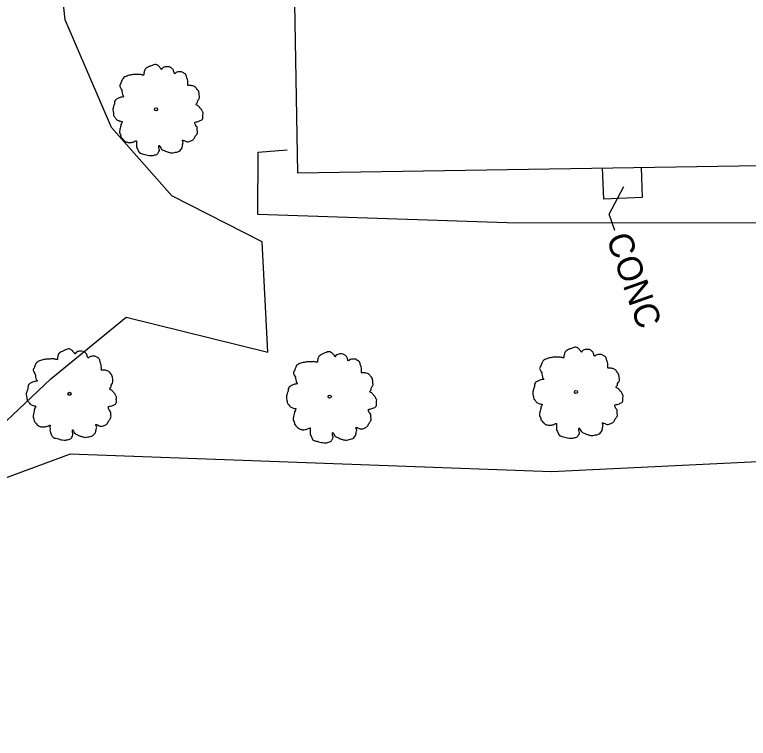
# Model space of a CAD drawing. Extents: x 2004847 to 2009016, y 1134161 to 1140101.
# Drawn here: x 2006332 to 2006449.6, y 1137314.8 to 1137430.7 of the extents above; entities that cross this region are included whole.
import ezdxf

# ---------------------------------------------------------------- set-up
doc = ezdxf.new("R2010")
doc.units = 0
for name, color, linetype in [('RD_EX_Bldg', 7, 'Continuous'), ('RD_EX_Conc', 7, 'Continuous'), ('RD_EX_Driveway', 7, 'Continuous'), ('RD_EX_VEG', 7, 'Continuous'), ('RD_Sketch3', 7, 'Continuous')]:
    doc.layers.add(name, color=color, linetype=linetype)

msp = doc.modelspace()

# ---------------------------------------------------------------- linework, layer by layer
at = {"layer": 'RD_EX_Bldg'}
msp.add_lwpolyline([(2006371.89, 1137715.52), (2006377.36, 1137405.37), (2007270.04, 1137419.53), (2007268.52, 1137729.51), (2007210.95, 1137728.61)], dxfattribs=at)
at = {"layer": 'RD_EX_Conc'}
for p, q in [((2006426.24, 1137406.15), (2006426.45, 1137401.15)), ((2006432.45, 1137406.25), (2006432.65, 1137401.41)), ((2006432.65, 1137401.41), (2006426.45, 1137401.15))]:
    msp.add_line(p, q, dxfattribs=at)
at = {"layer": 'RD_EX_Driveway'}
msp.add_lwpolyline([(2006320, 1137461.45), (2006324.08, 1137411.61), (2006324.34, 1137386.71), (2006308.63, 1137371.07), (2006287.09, 1137362.98), (2006291.81, 1137347.5), (2006305.24, 1137351.22), (2006324.46, 1137359.78), (2006337.82, 1137372.35), (2006349.89, 1137382.22), (2006372.62, 1137376.62), (2006371.69, 1137394.32), (2006357.21, 1137401.66), (2006347.58, 1137412.64), (2006340.11, 1137429.9), (2006337.43, 1137455.2)], dxfattribs=at)
at = {"layer": 'RD_EX_VEG'}
for points in [[(2007282.5, 1137416.98), (2007281.09, 1137410.1), (2007242.65, 1137408.85), (2007161.61, 1137408.11), (2007074.33, 1137407.29), (2006993.94, 1137406.09), (2006904.98, 1137405.1), (2006825.9, 1137403.95), (2006734.64, 1137402.12), (2006651.81, 1137401.28), (2006571.17, 1137400.1), (2006488.04, 1137397.36), (2006412.6, 1137397.32), (2006371.03, 1137398.69)], [(2006371.03, 1137398.69), (2006371.08, 1137408.7), (2006375.7, 1137409.05)], [(2006737.12, 1137362.87), (2006655.14, 1137367.42), (2006573.07, 1137360.44), (2006492.05, 1137361.03), (2006418.07, 1137357.44), (2006340.96, 1137360.31)], [(2006340.96, 1137360.31), (2006313.74, 1137350.25), (2006288.58, 1137344.89), (2006287.9, 1137319.66), (2006304.95, 1137291.42), (2006332.05, 1137276.17)]]:
    msp.add_lwpolyline(points, dxfattribs=at)
for centre, radius in [((2006354.7, 1137415.53), 0.25), ((2006354.68, 1137415.51), 0.0001), ((2006340.83, 1137369.96), 0.25), ((2006422.02, 1137370.24), 0.25), ((2006422.01, 1137370.22), 0.0001), ((2006340.82, 1137369.94), 0.0001), ((2006382.53, 1137369.52), 0.25), ((2006382.52, 1137369.5), 0.0001)]:
    msp.add_circle(centre, radius, dxfattribs=at)
for points in [[(2006354.83, 1137422.7), (2006354.53, 1137422.72), (2006354.2, 1137422.62), (2006353.95, 1137422.52), (2006353.73, 1137422.45), (2006353.5, 1137422.35), (2006353.2, 1137422.17), (2006352.98, 1137421.97), (2006352.85, 1137421.72), (2006352.8, 1137421.5), (2006352.75, 1137421.22), (2006352.75, 1137421.05), (2006352.63, 1137421.02), (2006352.48, 1137421.05), (2006352.23, 1137421.12), (2006351.98, 1137421.12), (2006351.73, 1137421.12), (2006351.38, 1137421.1), (2006351.03, 1137421.1), (2006350.76, 1137421.05), (2006350.43, 1137421), (2006350.06, 1137420.87), (2006349.71, 1137420.75), (2006349.41, 1137420.5), (2006349.16, 1137420.02), (2006349.03, 1137419.67), (2006348.88, 1137419.42), (2006349.03, 1137418.97), (2006349.21, 1137418.63), (2006349.23, 1137418.43), (2006349.31, 1137418), (2006349.41, 1137417.78), (2006349.53, 1137417.58), (2006349.46, 1137417.55), (2006349.08, 1137417.5), (2006348.78, 1137417.4), (2006348.36, 1137417.18), (2006348.13, 1137416.95), (2006348.03, 1137416.63), (2006348.01, 1137416.28), (2006347.91, 1137416.08), (2006347.83, 1137415.8), (2006347.81, 1137415.73), (2006347.76, 1137415.4), (2006347.86, 1137414.95), (2006347.88, 1137414.6), (2006348.01, 1137414.38), (2006348.16, 1137414.2), (2006348.33, 1137413.95), (2006348.73, 1137413.73), (2006349.06, 1137413.63), (2006349.26, 1137413.6), (2006349.08, 1137413.1), (2006349.03, 1137412.75), (2006348.91, 1137412.35), (2006348.91, 1137412.28), (2006348.86, 1137411.8), (2006349.01, 1137411.48), (2006349.08, 1137411.1), (2006349.26, 1137410.88), (2006349.53, 1137410.58), (2006349.86, 1137410.35), (2006350.36, 1137410.23), (2006350.76, 1137410.25), (2006351.33, 1137410.43), (2006351.58, 1137410.5), (2006351.56, 1137410.33), (2006351.58, 1137409.95), (2006351.58, 1137409.53), (2006351.73, 1137409.2), (2006351.83, 1137408.93), (2006351.98, 1137408.68), (2006352.31, 1137408.45), (2006352.7, 1137408.38), (2006353.13, 1137408.23), (2006353.58, 1137408.15), (2006354.08, 1137408.13), (2006354.68, 1137408.28), (2006354.95, 1137408.4), (2006355.05, 1137408.58), (2006355.25, 1137408.95), (2006355.2, 1137409.18), (2006355.23, 1137409.78), (2006355.33, 1137409.6), (2006355.5, 1137409.25), (2006356, 1137408.95), (2006356.4, 1137408.78), (2006356.88, 1137408.63), (2006357.18, 1137408.55), (2006357.65, 1137408.63), (2006358.03, 1137408.7), (2006358.4, 1137408.83), (2006358.7, 1137409.1), (2006358.88, 1137409.38), (2006358.93, 1137409.65), (2006359, 1137410.03), (2006359.05, 1137410.2)], [(2006359.05, 1137410.2), (2006358.98, 1137410.38), (2006358.93, 1137410.63), (2006359, 1137410.6), (2006359.18, 1137410.55), (2006359.45, 1137410.43), (2006359.68, 1137410.35), (2006360, 1137410.38), (2006360.28, 1137410.48), (2006360.73, 1137410.75), (2006361, 1137411.23), (2006361.28, 1137411.63), (2006361.35, 1137411.95), (2006361.3, 1137412.18), (2006361.28, 1137412.68), (2006361.08, 1137412.93), (2006361.03, 1137413.05), (2006360.93, 1137413.45), (2006361, 1137413.5), (2006361.28, 1137413.55), (2006361.65, 1137413.68), (2006361.93, 1137413.8), (2006362.15, 1137413.98), (2006362.23, 1137414.2), (2006362.2, 1137414.6), (2006362.25, 1137415), (2006362.18, 1137415.15), (2006362.08, 1137415.3), (2006362, 1137415.5), (2006361.85, 1137415.65), (2006361.75, 1137415.8), (2006361.65, 1137415.9), (2006361.53, 1137416.05), (2006361.35, 1137416.18), (2006361.2, 1137416.23), (2006361.15, 1137416.38), (2006361.3, 1137416.58), (2006361.35, 1137416.68), (2006361.38, 1137416.9), (2006361.6, 1137417.25), (2006361.65, 1137417.65), (2006361.6, 1137418.08), (2006361.55, 1137418.35), (2006361.4, 1137418.63), (2006361.2, 1137418.87), (2006361.08, 1137419.05), (2006360.9, 1137419.17), (2006360.58, 1137419.3), (2006360.33, 1137419.35), (2006359.98, 1137419.35), (2006359.78, 1137419.4), (2006359.8, 1137419.45), (2006359.8, 1137419.6), (2006359.8, 1137419.87), (2006359.73, 1137420.32), (2006359.58, 1137420.82), (2006359.58, 1137420.85), (2006359.48, 1137421.1), (2006359.25, 1137421.3), (2006359.08, 1137421.4), (2006358.88, 1137421.52), (2006358.63, 1137421.55), (2006358.33, 1137421.55), (2006358.05, 1137421.5), (2006357.85, 1137421.4), (2006357.68, 1137421.27), (2006357.6, 1137421.42), (2006357.5, 1137421.72), (2006357.45, 1137421.87), (2006357.3, 1137422.05), (2006357.08, 1137422.25), (2006356.63, 1137422.37), (2006356, 1137422.3), (2006355.7, 1137422.1), (2006355.55, 1137421.92), (2006355.5, 1137422.05), (2006355.3, 1137422.25), (2006355.2, 1137422.42), (2006355.03, 1137422.55), (2006354.88, 1137422.65), (2006354.78, 1137422.7)], [(2006340.96, 1137377.12), (2006340.66, 1137377.15), (2006340.34, 1137377.05), (2006340.09, 1137376.95), (2006339.86, 1137376.87), (2006339.64, 1137376.77), (2006339.34, 1137376.6), (2006339.11, 1137376.4), (2006338.99, 1137376.15), (2006338.94, 1137375.92), (2006338.89, 1137375.65), (2006338.89, 1137375.47), (2006338.76, 1137375.45), (2006338.61, 1137375.47), (2006338.36, 1137375.55), (2006338.11, 1137375.55), (2006337.86, 1137375.55), (2006337.51, 1137375.52), (2006337.16, 1137375.52), (2006336.89, 1137375.47), (2006336.56, 1137375.42), (2006336.19, 1137375.3), (2006335.84, 1137375.17), (2006335.54, 1137374.92), (2006335.29, 1137374.45), (2006335.17, 1137374.1), (2006335.02, 1137373.85), (2006335.17, 1137373.4), (2006335.34, 1137373.05), (2006335.37, 1137372.85), (2006335.44, 1137372.43), (2006335.54, 1137372.2), (2006335.67, 1137372), (2006335.59, 1137371.98), (2006335.22, 1137371.93), (2006334.92, 1137371.83), (2006334.49, 1137371.6), (2006334.27, 1137371.38), (2006334.17, 1137371.05), (2006334.14, 1137370.7), (2006334.04, 1137370.5), (2006333.97, 1137370.23), (2006333.94, 1137370.15), (2006333.89, 1137369.83), (2006333.99, 1137369.38), (2006334.02, 1137369.03), (2006334.14, 1137368.8), (2006334.29, 1137368.63), (2006334.47, 1137368.38), (2006334.87, 1137368.15), (2006335.19, 1137368.05), (2006335.39, 1137368.03), (2006335.22, 1137367.53), (2006335.17, 1137367.18), (2006335.04, 1137366.78), (2006335.04, 1137366.7), (2006334.99, 1137366.23), (2006335.14, 1137365.9), (2006335.22, 1137365.53), (2006335.39, 1137365.3), (2006335.67, 1137365), (2006335.99, 1137364.78), (2006336.49, 1137364.65), (2006336.89, 1137364.68), (2006337.46, 1137364.85), (2006337.71, 1137364.93), (2006337.69, 1137364.75), (2006337.71, 1137364.38), (2006337.71, 1137363.95), (2006337.86, 1137363.63), (2006337.96, 1137363.35), (2006338.11, 1137363.1), (2006338.44, 1137362.88), (2006338.84, 1137362.8), (2006339.26, 1137362.65), (2006339.71, 1137362.58), (2006340.21, 1137362.55), (2006340.81, 1137362.7), (2006341.09, 1137362.83), (2006341.19, 1137363), (2006341.39, 1137363.38), (2006341.34, 1137363.6), (2006341.36, 1137364.2), (2006341.46, 1137364.03), (2006341.64, 1137363.68), (2006342.14, 1137363.38), (2006342.54, 1137363.2), (2006343.01, 1137363.05), (2006343.31, 1137362.98), (2006343.79, 1137363.05), (2006344.16, 1137363.13), (2006344.54, 1137363.25), (2006344.84, 1137363.53), (2006345.01, 1137363.8), (2006345.06, 1137364.08), (2006345.14, 1137364.45), (2006345.19, 1137364.63)], [(2006345.19, 1137364.63), (2006345.11, 1137364.8), (2006345.06, 1137365.05), (2006345.14, 1137365.03), (2006345.31, 1137364.98), (2006345.59, 1137364.85), (2006345.81, 1137364.78), (2006346.14, 1137364.8), (2006346.41, 1137364.9), (2006346.86, 1137365.18), (2006347.14, 1137365.65), (2006347.41, 1137366.05), (2006347.49, 1137366.38), (2006347.44, 1137366.6), (2006347.41, 1137367.1), (2006347.21, 1137367.35), (2006347.16, 1137367.48), (2006347.06, 1137367.88), (2006347.14, 1137367.93), (2006347.41, 1137367.98), (2006347.78, 1137368.1), (2006348.06, 1137368.23), (2006348.28, 1137368.4), (2006348.36, 1137368.63), (2006348.33, 1137369.03), (2006348.38, 1137369.43), (2006348.31, 1137369.58), (2006348.21, 1137369.73), (2006348.13, 1137369.93), (2006347.98, 1137370.08), (2006347.88, 1137370.23), (2006347.78, 1137370.33), (2006347.66, 1137370.48), (2006347.49, 1137370.6), (2006347.34, 1137370.65), (2006347.29, 1137370.8), (2006347.44, 1137371), (2006347.49, 1137371.1), (2006347.51, 1137371.33), (2006347.74, 1137371.68), (2006347.78, 1137372.08), (2006347.74, 1137372.5), (2006347.69, 1137372.78), (2006347.54, 1137373.05), (2006347.34, 1137373.3), (2006347.21, 1137373.47), (2006347.04, 1137373.6), (2006346.71, 1137373.72), (2006346.46, 1137373.77), (2006346.11, 1137373.77), (2006345.91, 1137373.82), (2006345.94, 1137373.87), (2006345.94, 1137374.02), (2006345.94, 1137374.3), (2006345.86, 1137374.75), (2006345.71, 1137375.25), (2006345.71, 1137375.27), (2006345.61, 1137375.52), (2006345.39, 1137375.72), (2006345.21, 1137375.82), (2006345.01, 1137375.95), (2006344.76, 1137375.97), (2006344.46, 1137375.97), (2006344.19, 1137375.92), (2006343.99, 1137375.82), (2006343.81, 1137375.7), (2006343.74, 1137375.85), (2006343.64, 1137376.15), (2006343.59, 1137376.3), (2006343.44, 1137376.47), (2006343.21, 1137376.67), (2006342.76, 1137376.8), (2006342.14, 1137376.72), (2006341.84, 1137376.52), (2006341.69, 1137376.35), (2006341.64, 1137376.47), (2006341.44, 1137376.67), (2006341.34, 1137376.85), (2006341.16, 1137376.97), (2006341.01, 1137377.07), (2006340.91, 1137377.12)], [(2006422.15, 1137377.41), (2006421.85, 1137377.43), (2006421.53, 1137377.33), (2006421.28, 1137377.23), (2006421.05, 1137377.16), (2006420.83, 1137377.06), (2006420.53, 1137376.88), (2006420.3, 1137376.68), (2006420.18, 1137376.43), (2006420.13, 1137376.21), (2006420.08, 1137375.93), (2006420.08, 1137375.76), (2006419.95, 1137375.73), (2006419.8, 1137375.76), (2006419.55, 1137375.83), (2006419.3, 1137375.83), (2006419.05, 1137375.83), (2006418.7, 1137375.81), (2006418.35, 1137375.81), (2006418.08, 1137375.76), (2006417.75, 1137375.71), (2006417.38, 1137375.58), (2006417.03, 1137375.46), (2006416.73, 1137375.21), (2006416.48, 1137374.73), (2006416.35, 1137374.38), (2006416.2, 1137374.13), (2006416.35, 1137373.68), (2006416.53, 1137373.33), (2006416.55, 1137373.13), (2006416.63, 1137372.71), (2006416.73, 1137372.48), (2006416.85, 1137372.28), (2006416.78, 1137372.26), (2006416.4, 1137372.21), (2006416.1, 1137372.11), (2006415.68, 1137371.88), (2006415.45, 1137371.66), (2006415.35, 1137371.33), (2006415.33, 1137370.98), (2006415.23, 1137370.78), (2006415.15, 1137370.51), (2006415.13, 1137370.43), (2006415.08, 1137370.11), (2006415.18, 1137369.66), (2006415.2, 1137369.31), (2006415.33, 1137369.08), (2006415.48, 1137368.91), (2006415.65, 1137368.66), (2006416.05, 1137368.43), (2006416.38, 1137368.33), (2006416.58, 1137368.31), (2006416.4, 1137367.81), (2006416.35, 1137367.46), (2006416.23, 1137367.06), (2006416.23, 1137366.98), (2006416.18, 1137366.51), (2006416.33, 1137366.19), (2006416.4, 1137365.81), (2006416.58, 1137365.59), (2006416.85, 1137365.29), (2006417.18, 1137365.06), (2006417.68, 1137364.94), (2006418.08, 1137364.96), (2006418.65, 1137365.14), (2006418.9, 1137365.21), (2006418.88, 1137365.04), (2006418.9, 1137364.66), (2006418.9, 1137364.24), (2006419.05, 1137363.91), (2006419.15, 1137363.64), (2006419.3, 1137363.39), (2006419.63, 1137363.16), (2006420.03, 1137363.09), (2006420.45, 1137362.94), (2006420.9, 1137362.86), (2006421.4, 1137362.84), (2006422, 1137362.99), (2006422.28, 1137363.11), (2006422.38, 1137363.29), (2006422.58, 1137363.66), (2006422.53, 1137363.89), (2006422.55, 1137364.49), (2006422.65, 1137364.31), (2006422.83, 1137363.96), (2006423.33, 1137363.66), (2006423.73, 1137363.49), (2006424.2, 1137363.34), (2006424.5, 1137363.26), (2006424.97, 1137363.34), (2006425.35, 1137363.41), (2006425.72, 1137363.54), (2006426.02, 1137363.81), (2006426.2, 1137364.09), (2006426.25, 1137364.36), (2006426.32, 1137364.74), (2006426.37, 1137364.91)], [(2006426.37, 1137364.91), (2006426.3, 1137365.09), (2006426.25, 1137365.34), (2006426.32, 1137365.31), (2006426.5, 1137365.26), (2006426.77, 1137365.14), (2006427, 1137365.06), (2006427.32, 1137365.09), (2006427.6, 1137365.19), (2006428.05, 1137365.46), (2006428.32, 1137365.94), (2006428.6, 1137366.34), (2006428.67, 1137366.66), (2006428.62, 1137366.88), (2006428.6, 1137367.38), (2006428.4, 1137367.63), (2006428.35, 1137367.76), (2006428.25, 1137368.16), (2006428.32, 1137368.21), (2006428.6, 1137368.26), (2006428.97, 1137368.38), (2006429.25, 1137368.51), (2006429.47, 1137368.68), (2006429.55, 1137368.91), (2006429.52, 1137369.31), (2006429.57, 1137369.71), (2006429.5, 1137369.86), (2006429.4, 1137370.01), (2006429.32, 1137370.21), (2006429.17, 1137370.36), (2006429.07, 1137370.51), (2006428.97, 1137370.61), (2006428.85, 1137370.76), (2006428.67, 1137370.88), (2006428.52, 1137370.93), (2006428.47, 1137371.08), (2006428.62, 1137371.28), (2006428.67, 1137371.38), (2006428.7, 1137371.61), (2006428.92, 1137371.96), (2006428.97, 1137372.36), (2006428.92, 1137372.78), (2006428.87, 1137373.06), (2006428.72, 1137373.33), (2006428.52, 1137373.58), (2006428.4, 1137373.76), (2006428.22, 1137373.88), (2006427.9, 1137374.01), (2006427.65, 1137374.06), (2006427.3, 1137374.06), (2006427.1, 1137374.11), (2006427.12, 1137374.16), (2006427.12, 1137374.31), (2006427.12, 1137374.58), (2006427.05, 1137375.03), (2006426.9, 1137375.53), (2006426.9, 1137375.56), (2006426.8, 1137375.81), (2006426.57, 1137376.01), (2006426.4, 1137376.11), (2006426.2, 1137376.23), (2006425.95, 1137376.26), (2006425.65, 1137376.26), (2006425.37, 1137376.21), (2006425.17, 1137376.11), (2006425, 1137375.98), (2006424.92, 1137376.13), (2006424.82, 1137376.43), (2006424.77, 1137376.58), (2006424.62, 1137376.76), (2006424.4, 1137376.96), (2006423.95, 1137377.08), (2006423.33, 1137377.01), (2006423.03, 1137376.81), (2006422.88, 1137376.63), (2006422.83, 1137376.76), (2006422.63, 1137376.96), (2006422.53, 1137377.13), (2006422.35, 1137377.26), (2006422.2, 1137377.36), (2006422.1, 1137377.41)], [(2006382.66, 1137376.68), (2006382.36, 1137376.71), (2006382.04, 1137376.61), (2006381.79, 1137376.51), (2006381.56, 1137376.43), (2006381.34, 1137376.33), (2006381.04, 1137376.16), (2006380.81, 1137375.96), (2006380.69, 1137375.71), (2006380.64, 1137375.48), (2006380.59, 1137375.21), (2006380.59, 1137375.03), (2006380.46, 1137375.01), (2006380.31, 1137375.03), (2006380.06, 1137375.11), (2006379.81, 1137375.11), (2006379.56, 1137375.11), (2006379.21, 1137375.08), (2006378.86, 1137375.08), (2006378.59, 1137375.03), (2006378.26, 1137374.98), (2006377.89, 1137374.86), (2006377.54, 1137374.73), (2006377.24, 1137374.48), (2006376.99, 1137374.01), (2006376.87, 1137373.66), (2006376.72, 1137373.41), (2006376.87, 1137372.96), (2006377.04, 1137372.61), (2006377.07, 1137372.41), (2006377.14, 1137371.99), (2006377.24, 1137371.76), (2006377.37, 1137371.56), (2006377.29, 1137371.54), (2006376.92, 1137371.49), (2006376.62, 1137371.39), (2006376.19, 1137371.16), (2006375.97, 1137370.94), (2006375.87, 1137370.61), (2006375.84, 1137370.26), (2006375.74, 1137370.06), (2006375.67, 1137369.79), (2006375.64, 1137369.71), (2006375.59, 1137369.39), (2006375.69, 1137368.94), (2006375.72, 1137368.59), (2006375.84, 1137368.36), (2006375.99, 1137368.19), (2006376.17, 1137367.94), (2006376.57, 1137367.71), (2006376.89, 1137367.61), (2006377.09, 1137367.59), (2006376.92, 1137367.09), (2006376.87, 1137366.74), (2006376.74, 1137366.34), (2006376.74, 1137366.26), (2006376.69, 1137365.79), (2006376.84, 1137365.46), (2006376.92, 1137365.09), (2006377.09, 1137364.86), (2006377.37, 1137364.56), (2006377.69, 1137364.34), (2006378.19, 1137364.21), (2006378.59, 1137364.24), (2006379.16, 1137364.41), (2006379.41, 1137364.49), (2006379.39, 1137364.31), (2006379.41, 1137363.94), (2006379.41, 1137363.51), (2006379.56, 1137363.19), (2006379.66, 1137362.91), (2006379.81, 1137362.66), (2006380.14, 1137362.44), (2006380.54, 1137362.36), (2006380.96, 1137362.21), (2006381.41, 1137362.14), (2006381.91, 1137362.11), (2006382.51, 1137362.26), (2006382.79, 1137362.39), (2006382.89, 1137362.56), (2006383.09, 1137362.94), (2006383.04, 1137363.16), (2006383.06, 1137363.76), (2006383.16, 1137363.59), (2006383.34, 1137363.24), (2006383.84, 1137362.94), (2006384.24, 1137362.76), (2006384.71, 1137362.61), (2006385.01, 1137362.54), (2006385.49, 1137362.61), (2006385.86, 1137362.69), (2006386.24, 1137362.81), (2006386.54, 1137363.09), (2006386.71, 1137363.36), (2006386.76, 1137363.64), (2006386.84, 1137364.01), (2006386.89, 1137364.19)], [(2006386.89, 1137364.19), (2006386.81, 1137364.36), (2006386.76, 1137364.61), (2006386.84, 1137364.59), (2006387.01, 1137364.54), (2006387.29, 1137364.41), (2006387.51, 1137364.34), (2006387.84, 1137364.36), (2006388.11, 1137364.46), (2006388.56, 1137364.74), (2006388.84, 1137365.21), (2006389.11, 1137365.61), (2006389.19, 1137365.94), (2006389.14, 1137366.16), (2006389.11, 1137366.66), (2006388.91, 1137366.91), (2006388.86, 1137367.04), (2006388.76, 1137367.44), (2006388.84, 1137367.49), (2006389.11, 1137367.54), (2006389.48, 1137367.66), (2006389.76, 1137367.79), (2006389.98, 1137367.96), (2006390.06, 1137368.19), (2006390.03, 1137368.59), (2006390.08, 1137368.99), (2006390.01, 1137369.14), (2006389.91, 1137369.29), (2006389.83, 1137369.49), (2006389.68, 1137369.64), (2006389.58, 1137369.79), (2006389.48, 1137369.89), (2006389.36, 1137370.04), (2006389.19, 1137370.16), (2006389.04, 1137370.21), (2006388.99, 1137370.36), (2006389.14, 1137370.56), (2006389.19, 1137370.66), (2006389.21, 1137370.89), (2006389.44, 1137371.24), (2006389.48, 1137371.64), (2006389.44, 1137372.06), (2006389.39, 1137372.34), (2006389.24, 1137372.61), (2006389.04, 1137372.86), (2006388.91, 1137373.03), (2006388.74, 1137373.16), (2006388.41, 1137373.28), (2006388.16, 1137373.33), (2006387.81, 1137373.33), (2006387.61, 1137373.38), (2006387.64, 1137373.43), (2006387.64, 1137373.58), (2006387.64, 1137373.86), (2006387.56, 1137374.31), (2006387.41, 1137374.81), (2006387.41, 1137374.83), (2006387.31, 1137375.08), (2006387.09, 1137375.28), (2006386.91, 1137375.38), (2006386.71, 1137375.51), (2006386.46, 1137375.53), (2006386.16, 1137375.53), (2006385.89, 1137375.48), (2006385.69, 1137375.38), (2006385.51, 1137375.26), (2006385.44, 1137375.41), (2006385.34, 1137375.71), (2006385.29, 1137375.86), (2006385.14, 1137376.03), (2006384.91, 1137376.23), (2006384.46, 1137376.36), (2006383.84, 1137376.28), (2006383.54, 1137376.08), (2006383.39, 1137375.91), (2006383.34, 1137376.03), (2006383.14, 1137376.23), (2006383.04, 1137376.41), (2006382.86, 1137376.53), (2006382.71, 1137376.63), (2006382.61, 1137376.68)]]:
    msp.add_spline(points, degree=3, dxfattribs=at)
at = {"layer": 'RD_Sketch3'}
msp.add_lwpolyline([(2006428.25, 1137396.14), (2006427.33, 1137398.75), (2006429.68, 1137403.16)], dxfattribs=at)

# ---------------------------------------------------------------- texts
msp.add_text('CONC', height=4, rotation=289.4494, dxfattribs=at).set_placement((2006426.83, 1137394.94))

doc.saveas('drawing.dxf')
